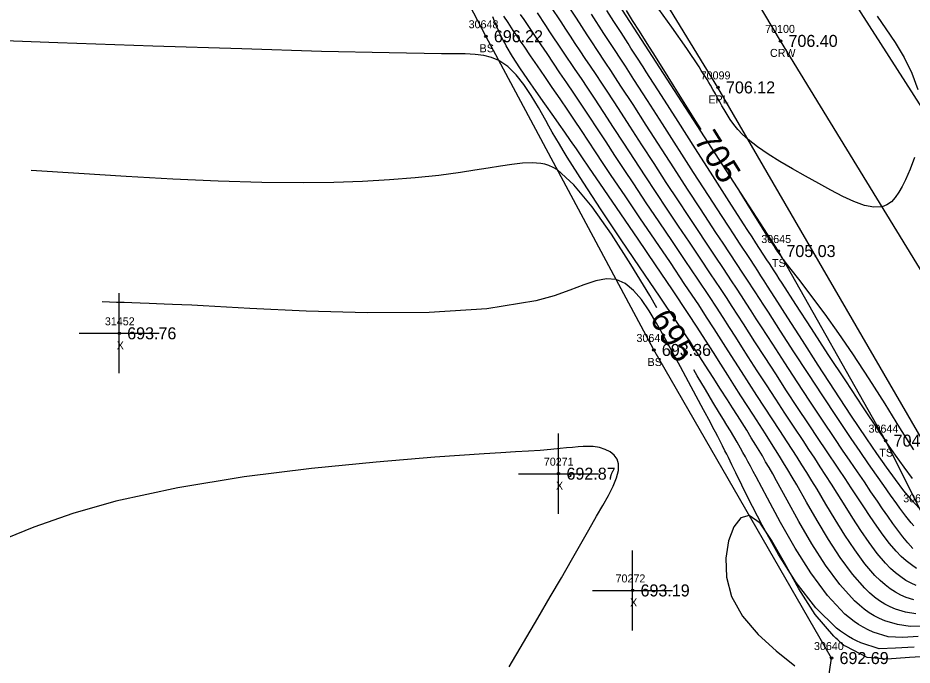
# Model space of a CAD drawing. Extents: x 1376587 to 1378239, y 1000335 to 1003031.
# Drawn here: x 1377213.6 to 1377325.3, y 1001675.7 to 1001756.6 of the extents above; entities that cross this region are included whole.
import ezdxf

# ---------------------------------------------------------------- set-up
doc = ezdxf.new("R2010")
doc.units = 0
for name, color, linetype in [('RD_DTM_BkLn1', 7, 'Continuous'), ('RD_DTM_BkLn2', 7, 'Continuous'), ('RD_DTM_BkLn_txCode', 7, 'Continuous'), ('RD_DTM_Major1', 7, 'Continuous'), ('RD_DTM_Major1_Lbl', 7, 'Continuous'), ('RD_DTM_Minor1', 7, 'Continuous'), ('RD_EX_Misc', 7, 'Continuous'), ('RD_EX_Misc_txCode', 7, 'Continuous'), ('RD_EX_Road', 7, 'Continuous'), ('RD_EX_Road_txCode', 7, 'Continuous'), ('RD_EX_TX_Misc_ELEV', 7, 'Continuous'), ('RD_EX_TX_Road_ELEV', 7, 'Continuous'), ('RD_HC_Survey_ELEV', 7, 'Continuous'), ('RD_HC_Survey_txCode', 7, 'Continuous'), ('RD_SMD_Locator', 7, 'Continuous')]:
    doc.layers.add(name, color=color, linetype=linetype)

msp = doc.modelspace()

# ---------------------------------------------------------------- linework, layer by layer
at = {"layer": 'RD_DTM_BkLn1'}
msp.add_lwpolyline([(1377340.41, 1001702.16), (1377308.87, 1001753.73), (1377278.25, 1001805.24), (1377245.96, 1001858.01), (1377214.82, 1001910.42), (1377182.97, 1001962.11), (1377151.24, 1002015.12), (1377120.39, 1002065.54), (1377089.62, 1002116.56), (1377055.77, 1002172.48), (1377024.27, 1002225.83), (1377004.13, 1002257.88), (1377003.45, 1002259.31)], dxfattribs=at)
at = {"layer": 'RD_DTM_BkLn2'}
for points in [[(1377331.19, 1001688.18), (1377328.36, 1001687.91), (1377326.34, 1001695.07), (1377322, 1001703.78), (1377308.61, 1001727.47), (1377286.37, 1001761.87), (1377261.46, 1001806.93)], [(1377312.74, 1001659.47), (1377315.24, 1001676.61), (1377293.05, 1001715.11), (1377272.07, 1001754.31), (1377247.28, 1001801.87)]]:
    msp.add_lwpolyline(points, dxfattribs=at)
at = {"layer": 'RD_DTM_Major1'}
for points in [[(1377298.95, 1001742.66), (1377298.3, 1001743.7), (1377296.54, 1001746.51), (1377294.84, 1001749.23), (1377293.24, 1001751.78), (1377292.21, 1001753.42), (1377291.26, 1001754.93), (1377290.4, 1001756.29), (1377289.62, 1001757.51)], [(1377325.84, 1001687.81), (1377325.21, 1001688.24), (1377324.58, 1001688.75), (1377323.95, 1001689.32), (1377323.33, 1001689.96), (1377322.5, 1001690.92), (1377321.69, 1001691.97), (1377320.88, 1001693.09), (1377320.08, 1001694.28), (1377319.27, 1001695.5), (1377318.46, 1001696.74), (1377317.7, 1001697.88), (1377316.94, 1001699.03), (1377316.15, 1001700.2), (1377314.52, 1001702.63), (1377313.66, 1001703.91), (1377312.35, 1001705.88), (1377311, 1001707.93), (1377309.63, 1001710.02), (1377308.27, 1001712.11), (1377306.94, 1001714.15), (1377305.68, 1001716.11), (1377304.94, 1001717.25), (1377304.23, 1001718.37), (1377303.52, 1001719.46), (1377302.82, 1001720.55), (1377302.11, 1001721.65), (1377301.37, 1001722.78), (1377300.14, 1001724.63), (1377298.85, 1001726.56), (1377297.51, 1001728.56), (1377296.13, 1001730.6), (1377294.73, 1001732.69), (1377293.32, 1001734.8), (1377291.96, 1001736.87), (1377290.62, 1001738.92), (1377289.3, 1001740.94), (1377288.03, 1001742.9), (1377286.8, 1001744.79), (1377285.63, 1001746.57), (1377284.8, 1001747.83), (1377284, 1001749.02), (1377283.23, 1001750.16), (1377281.78, 1001752.31), (1377281.09, 1001753.34), (1377280.58, 1001754.11), (1377280.07, 1001754.88), (1377279.56, 1001755.65), (1377278.51, 1001757.23)], [(1377293.44, 1001720.36), (1377292.53, 1001721.91), (1377290.17, 1001725.78), (1377287.75, 1001729.57), (1377285.35, 1001732.99), (1377283.07, 1001735.76), (1377281.01, 1001737.6), (1377280.47, 1001737.93), (1377279.94, 1001738.16), (1377279.43, 1001738.32), (1377278.92, 1001738.42), (1377278.41, 1001738.47), (1377277.88, 1001738.49), (1377276.66, 1001738.44), (1377275.33, 1001738.3), (1377273.9, 1001738.09), (1377272.35, 1001737.84), (1377270.69, 1001737.56), (1377268.9, 1001737.29), (1377266.18, 1001736.93), (1377263.23, 1001736.62), (1377260.05, 1001736.37), (1377256.66, 1001736.17), (1377253.07, 1001736.05), (1377249.3, 1001735.99), (1377244.08, 1001736.04), (1377238.62, 1001736.2), (1377232.96, 1001736.45), (1377227.15, 1001736.77), (1377221.24, 1001737.14), (1377215.28, 1001737.53)], [(1377325.5, 1001702.61), (1377323.78, 1001705.38), (1377321.92, 1001708.39), (1377319.96, 1001711.52), (1377317.92, 1001714.63), (1377316.16, 1001717.18), (1377314.43, 1001719.58), (1377312.8, 1001721.78), (1377311.31, 1001723.73), (1377310.04, 1001725.38), (1377309.05, 1001726.68), (1377308.86, 1001726.94), (1377308.69, 1001727.17), (1377308.53, 1001727.4), (1377308.38, 1001727.61), (1377308.24, 1001727.81), (1377308.1, 1001728.02), (1377308.07, 1001728.06), (1377308.04, 1001728.11), (1377308.01, 1001728.15), (1377307.98, 1001728.2), (1377307.95, 1001728.25), (1377307.92, 1001728.29), (1377307.87, 1001728.36), (1377307.82, 1001728.44), (1377307.77, 1001728.51), (1377307.67, 1001728.67), (1377307.62, 1001728.75), (1377307.08, 1001729.58), (1377306.48, 1001730.55), (1377305.79, 1001731.65), (1377304.16, 1001734.28), (1377303.7, 1001735.02)], [(1377326.06, 1001679.29), (1377324.13, 1001679.16), (1377322.33, 1001679.27), (1377320.43, 1001679.86), (1377319.81, 1001680.13), (1377319.21, 1001680.45), (1377318.63, 1001680.8), (1377318.05, 1001681.19), (1377317.48, 1001681.63), (1377316.92, 1001682.11), (1377314.74, 1001684.43), (1377312.65, 1001687.24), (1377310.68, 1001690.35), (1377308.87, 1001693.53), (1377307.24, 1001696.57), (1377305.84, 1001699.26), (1377305.47, 1001699.94), (1377305.13, 1001700.59), (1377304.8, 1001701.19), (1377304.48, 1001701.77), (1377304.18, 1001702.31), (1377303.88, 1001702.83), (1377303.46, 1001703.57), (1377303.04, 1001704.29), (1377302.61, 1001704.99), (1377302.18, 1001705.7), (1377301.74, 1001706.44), (1377301.27, 1001707.21), (1377300.42, 1001708.6), (1377299.49, 1001710.15), (1377298.46, 1001711.88), (1377298.03, 1001712.61)]]:
    msp.add_lwpolyline(points, dxfattribs=at)
at = {"layer": 'RD_DTM_Minor1'}
for points in [[(1377325.38, 1001690.31), (1377324.77, 1001690.99), (1377324.14, 1001691.76), (1377323.51, 1001692.58), (1377322.89, 1001693.44), (1377322.26, 1001694.34), (1377321.62, 1001695.27), (1377320.97, 1001696.22), (1377320.17, 1001697.4), (1377319.34, 1001698.62), (1377318.47, 1001699.89), (1377317.57, 1001701.21), (1377316.63, 1001702.59), (1377315.64, 1001704.05), (1377314.13, 1001706.32), (1377312.55, 1001708.7), (1377310.96, 1001711.11), (1377309.4, 1001713.51), (1377307.9, 1001715.82), (1377306.5, 1001717.98), (1377305.84, 1001719.01), (1377305.2, 1001720), (1377304.59, 1001720.95), (1377303.98, 1001721.89), (1377303.38, 1001722.82), (1377302.76, 1001723.76), (1377301.76, 1001725.27), (1377300.71, 1001726.84), (1377299.62, 1001728.47), (1377298.49, 1001730.16), (1377297.32, 1001731.92), (1377296.11, 1001733.75), (1377294.6, 1001736.04), (1377293.07, 1001738.4), (1377291.55, 1001740.76), (1377290.05, 1001743.07), (1377288.62, 1001745.27), (1377287.29, 1001747.32), (1377286.54, 1001748.46), (1377285.83, 1001749.54), (1377285.15, 1001750.56), (1377284.49, 1001751.54), (1377283.86, 1001752.49), (1377283.24, 1001753.42), (1377282.65, 1001754.31), (1377282.06, 1001755.21), (1377281.46, 1001756.12), (1377280.2, 1001758.03)], [(1377325.51, 1001693.13), (1377325.18, 1001693.51), (1377324.85, 1001693.91), (1377324.51, 1001694.36), (1377324.15, 1001694.83), (1377323.78, 1001695.34), (1377323.38, 1001695.88), (1377322.61, 1001696.96), (1377321.76, 1001698.16), (1377320.84, 1001699.47), (1377319.86, 1001700.89), (1377318.81, 1001702.42), (1377317.7, 1001704.05), (1377315.96, 1001706.65), (1377314.15, 1001709.38), (1377312.33, 1001712.15), (1377310.55, 1001714.88), (1377308.87, 1001717.47), (1377307.35, 1001719.82), (1377306.77, 1001720.72), (1377305.69, 1001722.38), (1377304.68, 1001723.94), (1377304.18, 1001724.7), (1377303.38, 1001725.91), (1377301.71, 1001728.44), (1377300.81, 1001729.78), (1377299.87, 1001731.21), (1377298.87, 1001732.73), (1377297.25, 1001735.21), (1377295.55, 1001737.85), (1377292.09, 1001743.22), (1377290.45, 1001745.77), (1377288.94, 1001748.09), (1377288.28, 1001749.1), (1377287.66, 1001750.05), (1377287.07, 1001750.95), (1377285.94, 1001752.66), (1377285.4, 1001753.48), (1377284.73, 1001754.5), (1377284.06, 1001755.53), (1377283.37, 1001756.58), (1377282.65, 1001757.68)], [(1377325.34, 1001699.06), (1377324.3, 1001700.45), (1377323.21, 1001701.98), (1377322.06, 1001703.65), (1377321.92, 1001703.87), (1377321.77, 1001704.08), (1377321.63, 1001704.3), (1377321.33, 1001704.74), (1377321.18, 1001704.96), (1377319.15, 1001708), (1377317.01, 1001711.24), (1377314.84, 1001714.56), (1377312.74, 1001717.79), (1377310.78, 1001720.81), (1377309.06, 1001723.47), (1377308.72, 1001724), (1377308.39, 1001724.5), (1377308.08, 1001724.99), (1377307.48, 1001725.92), (1377307.18, 1001726.38), (1377306.72, 1001727.08), (1377306.26, 1001727.79), (1377305.8, 1001728.51), (1377305.31, 1001729.26), (1377304.8, 1001730.05), (1377304.26, 1001730.89), (1377302.46, 1001733.68), (1377300.43, 1001736.85), (1377298.27, 1001740.23), (1377296.09, 1001743.64), (1377294, 1001746.91), (1377292.11, 1001749.86), (1377291.7, 1001750.49), (1377290.92, 1001751.7), (1377290.19, 1001752.84), (1377289.84, 1001753.39), (1377288.95, 1001754.77), (1377288.07, 1001756.14), (1377287.18, 1001757.53)], [(1377325.59, 1001739.15), (1377325.05, 1001737.71), (1377324.46, 1001736.38), (1377324.06, 1001735.55), (1377323.64, 1001734.81), (1377323.2, 1001734.16), (1377322.71, 1001733.63), (1377322.16, 1001733.24), (1377321.55, 1001732.99), (1377320.52, 1001732.94), (1377319.34, 1001733.17), (1377318.04, 1001733.65), (1377316.64, 1001734.3), (1377315.17, 1001735.08), (1377313.64, 1001735.92), (1377312, 1001736.84), (1377310.37, 1001737.76), (1377308.79, 1001738.68), (1377307.32, 1001739.59), (1377305.99, 1001740.5), (1377304.84, 1001741.4), (1377304.14, 1001742.04), (1377303.54, 1001742.67), (1377303.03, 1001743.29), (1377302.58, 1001743.91), (1377302.19, 1001744.53), (1377301.82, 1001745.14), (1377301.55, 1001745.62), (1377301.29, 1001746.1), (1377301.02, 1001746.59), (1377300.73, 1001747.11), (1377300.43, 1001747.64), (1377300.11, 1001748.21), (1377299.91, 1001748.55), (1377299.69, 1001748.9), (1377299.47, 1001749.27), (1377299.23, 1001749.65), (1377298.98, 1001750.05), (1377298.7, 1001750.48), (1377297.17, 1001752.77), (1377295.29, 1001755.46), (1377293.15, 1001758.46)], [(1377325.76, 1001682.13), (1377324.48, 1001682.35), (1377323.24, 1001682.72), (1377322.56, 1001683.01), (1377321.9, 1001683.35), (1377321.25, 1001683.75), (1377320.62, 1001684.22), (1377319.99, 1001684.75), (1377319.38, 1001685.35), (1377317.84, 1001687.11), (1377316.33, 1001689.18), (1377314.87, 1001691.44), (1377313.46, 1001693.78), (1377312.13, 1001696.08), (1377310.89, 1001698.25), (1377310.33, 1001699.21), (1377309.79, 1001700.12), (1377309.26, 1001700.99), (1377308.75, 1001701.83), (1377308.24, 1001702.64), (1377307.74, 1001703.44), (1377307, 1001704.61), (1377306.25, 1001705.78), (1377305.49, 1001706.96), (1377303.93, 1001709.37), (1377303.13, 1001710.61), (1377302.28, 1001711.95), (1377301.41, 1001713.33), (1377300.48, 1001714.79), (1377299.5, 1001716.32), (1377298.46, 1001717.95), (1377297.33, 1001719.68), (1377295.38, 1001722.63), (1377293.27, 1001725.76), (1377291.1, 1001728.97), (1377288.93, 1001732.14), (1377286.86, 1001735.17), (1377284.95, 1001737.94), (1377284.14, 1001739.12), (1377283.37, 1001740.23), (1377282.64, 1001741.29), (1377281.93, 1001742.31), (1377281.23, 1001743.31), (1377280.54, 1001744.3), (1377279.44, 1001745.85), (1377278.36, 1001747.4), (1377277.3, 1001748.91), (1377276.31, 1001750.38), (1377275.41, 1001751.79), (1377274.62, 1001753.12), (1377274.42, 1001753.47), (1377274.24, 1001753.81), (1377274.06, 1001754.15), (1377273.9, 1001754.48), (1377273.74, 1001754.82), (1377273.59, 1001755.15), (1377273.36, 1001755.67), (1377273.15, 1001756.21), (1377272.94, 1001756.75)], [(1377325.52, 1001683.9), (1377324.56, 1001684.19), (1377323.88, 1001684.48), (1377323.22, 1001684.83), (1377322.57, 1001685.25), (1377321.93, 1001685.74), (1377321.3, 1001686.29), (1377320.67, 1001686.91), (1377319.4, 1001688.4), (1377318.14, 1001690.12), (1377316.91, 1001691.98), (1377315.7, 1001693.91), (1377314.54, 1001695.85), (1377313.43, 1001697.72), (1377312.79, 1001698.77), (1377312.16, 1001699.79), (1377311.54, 1001700.77), (1377310.93, 1001701.73), (1377310.32, 1001702.68), (1377309.7, 1001703.63), (1377308.78, 1001705.05), (1377307.84, 1001706.49), (1377306.89, 1001707.95), (1377305.93, 1001709.43), (1377304.96, 1001710.92), (1377304, 1001712.41), (1377303.17, 1001713.71), (1377302.33, 1001715.02), (1377301.47, 1001716.37), (1377300.58, 1001717.76), (1377299.64, 1001719.21), (1377298.65, 1001720.74), (1377296.94, 1001723.31), (1377295.11, 1001726.04), (1377293.22, 1001728.83), (1377291.32, 1001731.63), (1377289.48, 1001734.35), (1377287.74, 1001736.92), (1377286.73, 1001738.42), (1377285.78, 1001739.85), (1377284.87, 1001741.22), (1377284, 1001742.54), (1377283.15, 1001743.82), (1377282.31, 1001745.07), (1377281.34, 1001746.51), (1377280.37, 1001747.92), (1377279.43, 1001749.29), (1377278.53, 1001750.61), (1377277.66, 1001751.87), (1377276.84, 1001753.07), (1377276.5, 1001753.57), (1377276.16, 1001754.07), (1377275.83, 1001754.56), (1377275.5, 1001755.04), (1377274.84, 1001756.03), (1377274.32, 1001756.82)], [(1377325.83, 1001685.67), (1377325.17, 1001685.96), (1377324.52, 1001686.32), (1377323.88, 1001686.75), (1377323.24, 1001687.25), (1377322.62, 1001687.82), (1377321.99, 1001688.45), (1377320.95, 1001689.67), (1377319.93, 1001691.05), (1377318.91, 1001692.53), (1377317.91, 1001694.08), (1377316.93, 1001695.65), (1377315.95, 1001697.21), (1377315.25, 1001698.33), (1377314.55, 1001699.42), (1377313.84, 1001700.5), (1377313.14, 1001701.58), (1377312.42, 1001702.67), (1377311.68, 1001703.78), (1377310.57, 1001705.47), (1377309.42, 1001707.21), (1377308.27, 1001708.97), (1377307.11, 1001710.75), (1377305.96, 1001712.51), (1377304.84, 1001714.25), (1377304.05, 1001715.48), (1377303.27, 1001716.7), (1377302.49, 1001717.93), (1377301.69, 1001719.17), (1377300.86, 1001720.45), (1377300, 1001721.77), (1377298.54, 1001723.97), (1377296.98, 1001726.29), (1377295.37, 1001728.68), (1377293.73, 1001731.1), (1377292.11, 1001733.51), (1377290.53, 1001735.86), (1377289.33, 1001737.67), (1377288.18, 1001739.41), (1377287.08, 1001741.1), (1377286.01, 1001742.73), (1377284.97, 1001744.31), (1377283.96, 1001745.83), (1377283.06, 1001747.19), (1377282.18, 1001748.5), (1377281.32, 1001749.76), (1377279.71, 1001752.14), (1377278.96, 1001753.25), (1377278.52, 1001753.89), (1377278.1, 1001754.52), (1377277.68, 1001755.15), (1377276.84, 1001756.4), (1377276.4, 1001757.04)], [(1377326.22, 1001695.31), (1377325.28, 1001696.32), (1377324.28, 1001697.52), (1377323.22, 1001698.91), (1377322.09, 1001700.46), (1377320.9, 1001702.16), (1377319.65, 1001704), (1377317.67, 1001706.96), (1377315.63, 1001710.08), (1377313.59, 1001713.22), (1377311.62, 1001716.28), (1377309.79, 1001719.13), (1377308.18, 1001721.66), (1377307.71, 1001722.39), (1377307.26, 1001723.08), (1377306.84, 1001723.74), (1377306.43, 1001724.37), (1377306.04, 1001724.98), (1377305.65, 1001725.59), (1377305.03, 1001726.53), (1377303.76, 1001728.46), (1377303.09, 1001729.49), (1377302.37, 1001730.59), (1377301.59, 1001731.78), (1377299.89, 1001734.4), (1377298.02, 1001737.3), (1377294.12, 1001743.38), (1377292.26, 1001746.28), (1377290.57, 1001748.89), (1377289.49, 1001750.56), (1377288.99, 1001751.33), (1377288.04, 1001752.79), (1377286.82, 1001754.67), (1377285.27, 1001757.05)], [(1377320.94, 1001756.82), (1377322.04, 1001755.25), (1377323.19, 1001753.51), (1377324.3, 1001751.64), (1377325.27, 1001749.68), (1377326.02, 1001747.64)], [(1377326.64, 1001680.59), (1377325.08, 1001680.57), (1377323.46, 1001680.82), (1377321.9, 1001681.28), (1377321.23, 1001681.56), (1377320.58, 1001681.89), (1377319.95, 1001682.27), (1377319.33, 1001682.71), (1377318.72, 1001683.2), (1377318.12, 1001683.75), (1377316.28, 1001685.79), (1377314.49, 1001688.22), (1377312.78, 1001690.9), (1377311.17, 1001693.66), (1377309.69, 1001696.33), (1377308.36, 1001698.77), (1377307.89, 1001699.61), (1377307.44, 1001700.41), (1377307.01, 1001701.15), (1377306.6, 1001701.86), (1377306.2, 1001702.54), (1377305.8, 1001703.2), (1377305.22, 1001704.14), (1377304.65, 1001705.07), (1377304.07, 1001705.99), (1377303.48, 1001706.92), (1377302.87, 1001707.88), (1377302.23, 1001708.87), (1377301.38, 1001710.21), (1377300.47, 1001711.65), (1377299.48, 1001713.19), (1377298.41, 1001714.85), (1377297.25, 1001716.63), (1377295.98, 1001718.55), (1377293.76, 1001721.85), (1377291.36, 1001725.38), (1377288.9, 1001729.01), (1377286.48, 1001732.62), (1377284.22, 1001736.06), (1377282.23, 1001739.21), (1377281.73, 1001740.03), (1377281.26, 1001740.82), (1377280.81, 1001741.59), (1377280.37, 1001742.34), (1377279.95, 1001743.08), (1377279.54, 1001743.8), (1377278.64, 1001745.39), (1377277.74, 1001746.9), (1377276.82, 1001748.29), (1377275.85, 1001749.51), (1377274.81, 1001750.53), (1377273.68, 1001751.28), (1377272.79, 1001751.66), (1377271.81, 1001751.9), (1377270.73, 1001752.03), (1377269.5, 1001752.1), (1377268.12, 1001752.12), (1377266.54, 1001752.13), (1377259.99, 1001752.22), (1377251.54, 1001752.42), (1377241.58, 1001752.72), (1377230.48, 1001753.08), (1377218.63, 1001753.5), (1377206.4, 1001753.93)], [(1377325.58, 1001677.98), (1377323.22, 1001677.83), (1377321.18, 1001677.78), (1377318.88, 1001678.53), (1377318.36, 1001678.77), (1377317.85, 1001679.03), (1377317.34, 1001679.32), (1377316.85, 1001679.64), (1377316.36, 1001679.98), (1377315.88, 1001680.35), (1377313.27, 1001682.89), (1377310.84, 1001686.05), (1377308.6, 1001689.57), (1377306.57, 1001693.2), (1377304.8, 1001696.68), (1377303.3, 1001699.75), (1377303.05, 1001700.26), (1377302.81, 1001700.74), (1377302.58, 1001701.21), (1377302.36, 1001701.66), (1377302.15, 1001702.09), (1377301.93, 1001702.52), (1377301.63, 1001703.12), (1377301.33, 1001703.7), (1377301.03, 1001704.28), (1377300.73, 1001704.85), (1377300.42, 1001705.43), (1377300.11, 1001706.03), (1377299.26, 1001707.63), (1377298.34, 1001709.34), (1377297.38, 1001711.14), (1377296.37, 1001713), (1377295.34, 1001714.9), (1377294.3, 1001716.82), (1377293.39, 1001718.45), (1377292.47, 1001720), (1377291.52, 1001721.4), (1377290.52, 1001722.56), (1377289.46, 1001723.43), (1377288.33, 1001723.92), (1377287.13, 1001724), (1377285.79, 1001723.74), (1377284.29, 1001723.23), (1377282.57, 1001722.59), (1377280.59, 1001721.89), (1377278.3, 1001721.24), (1377272.2, 1001720.25), (1377265.01, 1001719.8), (1377257.3, 1001719.76), (1377249.64, 1001719.97), (1377242.6, 1001720.31), (1377236.75, 1001720.63), (1377235.35, 1001720.7), (1377234.09, 1001720.76), (1377232.94, 1001720.81), (1377231.89, 1001720.85), (1377230.92, 1001720.89), (1377230.02, 1001720.92), (1377228.91, 1001720.96), (1377227.87, 1001721), (1377226.89, 1001721.03), (1377225.96, 1001721.06), (1377225.05, 1001721.09), (1377224.15, 1001721.12)], [(1377274.98, 1001675.5), (1377278.58, 1001681.58), (1377280.12, 1001684.24), (1377281.51, 1001686.65), (1377282.76, 1001688.83), (1377284.94, 1001692.64), (1377285.9, 1001694.32), (1377286.68, 1001695.66), (1377287.38, 1001696.91), (1377287.97, 1001698.07), (1377288.4, 1001699.12), (1377288.64, 1001700.06), (1377288.65, 1001700.88), (1377288.46, 1001701.47), (1377288.09, 1001701.97), (1377287.59, 1001702.38), (1377286.97, 1001702.69), (1377286.26, 1001702.91), (1377285.49, 1001703.03), (1377284.87, 1001703.06), (1377284.24, 1001703.05), (1377283.58, 1001703.01), (1377282.88, 1001702.94), (1377282.15, 1001702.86), (1377281.37, 1001702.78), (1377280.18, 1001702.67), (1377278.86, 1001702.56), (1377277.4, 1001702.46), (1377275.76, 1001702.36), (1377273.92, 1001702.24), (1377271.85, 1001702.11), (1377265.68, 1001701.7), (1377258.35, 1001701.1), (1377250.28, 1001700.3), (1377241.9, 1001699.24), (1377233.62, 1001697.89), (1377225.86, 1001696.21), (1377220.5, 1001694.69), (1377215.61, 1001692.98), (1377211.08, 1001691.13)], [(1377327.79, 1001676.86), (1377324.96, 1001676.67), (1377322.19, 1001676.49), (1377319.71, 1001676.68), (1377317.08, 1001678.05), (1377316.76, 1001678.19), (1377316.51, 1001678.39), (1377316.29, 1001678.65), (1377316.03, 1001678.87), (1377315.78, 1001679.1), (1377315.53, 1001679.33), (1377313.21, 1001682.07), (1377311.17, 1001685.26), (1377309.37, 1001688.49), (1377307.76, 1001691.36), (1377306.31, 1001693.48), (1377304.96, 1001694.44), (1377303.93, 1001694.14), (1377303.03, 1001693.02), (1377302.37, 1001691.26), (1377302.04, 1001689.08), (1377302.13, 1001686.7), (1377302.74, 1001684.32), (1377304.12, 1001681.83), (1377306.06, 1001679.57), (1377308.32, 1001677.52), (1377310.65, 1001675.64)]]:
    msp.add_lwpolyline(points, dxfattribs=at)
at = {"layer": 'RD_EX_Misc'}
for p, q in [((1377226.28, 1001712.19), (1377226.28, 1001722.19)), ((1377221.28, 1001717.19), (1377231.28, 1001717.19)), ((1377281.14, 1001694.65), (1377281.14, 1001704.65)), ((1377276.14, 1001699.65), (1377286.14, 1001699.65)), ((1377290.39, 1001680.06), (1377290.39, 1001690.06)), ((1377285.39, 1001685.06), (1377295.39, 1001685.06))]:
    msp.add_line(p, q, dxfattribs=at)
at = {"layer": 'RD_EX_Road'}
for points in [[(1377350.34, 1001708.26), (1377317.92, 1001758.89), (1377286.96, 1001809.89), (1377254.77, 1001863.4), (1377224.6, 1001914.86), (1377192.26, 1001967.36), (1377160.97, 1002019.84), (1377129.72, 1002070.66), (1377099.39, 1002121.71), (1377064.16, 1002179.08), (1377033.49, 1002231.09), (1377014.7, 1002262.97), (1377013.31, 1002264.91)], [(1377330.92, 1001696.38), (1377301.06, 1001747.92), (1377269.09, 1001800.22), (1377238.03, 1001851.8), (1377206.51, 1001905.09), (1377174.78, 1001956.21), (1377142.24, 1002010.21), (1377112.37, 1002059.86), (1377081.07, 1002112.14), (1377047.75, 1002166.27), (1377015.04, 1002220.7), (1376995.39, 1002252.52), (1376994.75, 1002253.91)]]:
    msp.add_lwpolyline(points, dxfattribs=at)
at = {"layer": 'RD_SMD_Locator'}
for centre in [(1377272.07, 1001754.31), (1377308.87, 1001753.73), (1377301.06, 1001747.92), (1377308.61, 1001727.47), (1377226.28, 1001717.19), (1377293.05, 1001715.11), (1377322, 1001703.78), (1377281.14, 1001699.65), (1377282.53, 1001699.42), (1377290.39, 1001685.06), (1377315.24, 1001676.61)]:
    msp.add_circle(centre, 0.15, dxfattribs=at)

# ---------------------------------------------------------------- texts
at = {"layer": 'RD_DTM_BkLn_txCode'}
for s, p in [('30648', (1377269.92, 1001755.31)), ('BS', (1377271.29, 1001752.31)), ('30645', (1377306.47, 1001728.47)), ('TS', (1377307.81, 1001725.47)), ('30646', (1377290.88, 1001716.11)), ('BS', (1377292.27, 1001713.11)), ('30644', (1377319.86, 1001704.78)), ('TS', (1377321.21, 1001701.78)), ('30643', (1377324.19, 1001696.07)), ('30640', (1377313.05, 1001677.61))]:
    msp.add_text(s, height=1, dxfattribs=at).set_placement(p)
at = {"layer": 'RD_DTM_Major1_Lbl'}
for s, rotation, p in [('705', 301.8982, (1377297.99, 1001741.36)), ('695', 300.6063, (1377292.47, 1001719.06))]:
    msp.add_text(s, height=3, rotation=rotation, dxfattribs=at).set_placement(p)
at = {"layer": 'RD_EX_Misc_txCode'}
for s, p in [('31452', (1377224.49, 1001718.19)), ('X', (1377225.97, 1001715.19)), ('70271', (1377279.31, 1001700.65)), ('X', (1377280.83, 1001697.65)), ('70272', (1377288.27, 1001686.06)), ('X', (1377290.08, 1001683.06))]:
    msp.add_text(s, height=1, dxfattribs=at).set_placement(p)
at = {"layer": 'RD_EX_Road_txCode'}
for s, p in [('70099', (1377298.9, 1001748.92)), ('EPL', (1377299.86, 1001745.92))]:
    msp.add_text(s, height=1, dxfattribs=at).set_placement(p)
at = {"layer": 'RD_EX_TX_Misc_ELEV'}
for s, p in [('696.22', (1377273.07, 1001753.56)), ('705.03', (1377309.61, 1001726.72)), ('693.76', (1377227.28, 1001716.44)), ('693.36', (1377294.05, 1001714.36)), ('704.01', (1377323, 1001703.03)), ('692.87', (1377282.14, 1001698.9)), ('693.19', (1377291.39, 1001684.31)), ('692.69', (1377316.24, 1001675.86))]:
    msp.add_text(s, height=1.5, dxfattribs=at).set_placement(p)
at = {"layer": 'RD_EX_TX_Road_ELEV'}
msp.add_text('706.12', height=1.5, dxfattribs=at).set_placement((1377302.06, 1001747.17))
at = {"layer": 'RD_HC_Survey_ELEV'}
msp.add_text('706.40', height=1.5, dxfattribs=at).set_placement((1377309.87, 1001752.98))
at = {"layer": 'RD_HC_Survey_txCode'}
for s, p in [('70100', (1377306.95, 1001754.73)), ('CRW', (1377307.55, 1001751.73))]:
    msp.add_text(s, height=1, dxfattribs=at).set_placement(p)

doc.saveas('drawing.dxf')
